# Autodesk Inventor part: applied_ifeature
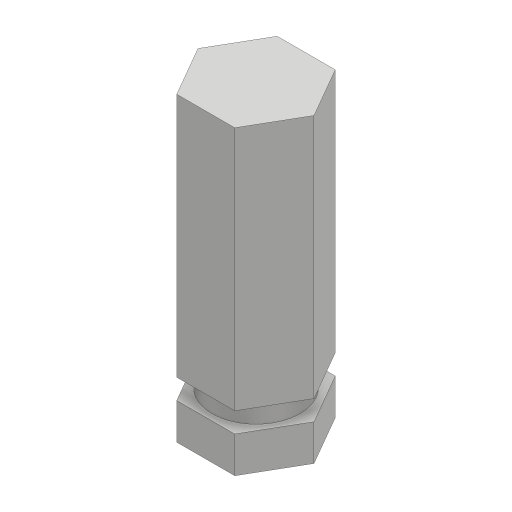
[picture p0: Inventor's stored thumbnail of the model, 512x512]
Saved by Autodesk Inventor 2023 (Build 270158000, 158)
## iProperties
Created: 2016-08
Part Number: applied_ifeature
Material: Generic
Document SubType Name: Modeling
Designer: Sandeep
Density: 1 g/cm^3
Appearance: Default
Author: Sandeep
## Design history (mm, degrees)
sketch "Sketch1"
  geometry: L1 (28.868, 0)-(14.434, -25); L2 (14.434, -25)-(-14.434, -25); L3 (-14.434, -25)-(-28.868, 0); L4 (-28.868, 0)-(-14.434, 25); L5 (-14.434, 25)-(14.434, 25); L6 (14.434, 25)-(28.868, 0); 2 further points
  constraints: 12 end point, 1 coincident, 13 other
  dimensions: "d0" = 50 distance between parallel lines of L2 L5
extrude "Extrusion1" new body sketch "Sketch1" distance "d1" = 150; taper "d2" = 0 deg
feature "iFeature4:1"
body "Solid1"
